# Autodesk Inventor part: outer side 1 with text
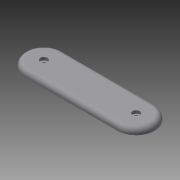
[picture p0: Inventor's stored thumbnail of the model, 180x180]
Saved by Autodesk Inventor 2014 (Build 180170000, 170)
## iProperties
Created: 2015-01
Part Number: outer side 1 with text
Material: Generic
Document SubType Name: Modeling
Designer: Drano
Density: 1 g/cm^3
Appearance: Default
Author: Drano
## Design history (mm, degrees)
sketch "Sketch1"
  geometry: L1 (-39.389, -16.629)-(37.611, -16.629); L2 (-39.389, 14.371)-(37.611, 14.371); C1 r 1.5 at (-39.389, -1.129); C2 r 1.5 at (37.611, -1.129); A1 r 15.5 centre (37.611, -1.129) between (37.611, -16.629) and (37.611, 14.371); A2 r 15.5 centre (-39.389, -1.129) between (-39.389, 14.371) and (-39.389, -16.629); 1 further point
  constraints: 4 centre point, 4 end point, 4 point on circle
extrude "Extrusion1" new body sketch "Sketch1" distance "d0" = 5; taper "d1" = 0 deg
fillet "Fillet1" dims "d2" = 4
feature "Lip1" dims "d3" = 2.5, "d4" = 1.5, "d5" = 0, "d6" = 0, "d7" = 0, "d8" = 0
feature "Lip2" dims "d9" = 2.5, "d10" = 1.5, "d11" = 0, "d12" = 0, "d13" = 0, "d14" = 0
body "Solid1"
